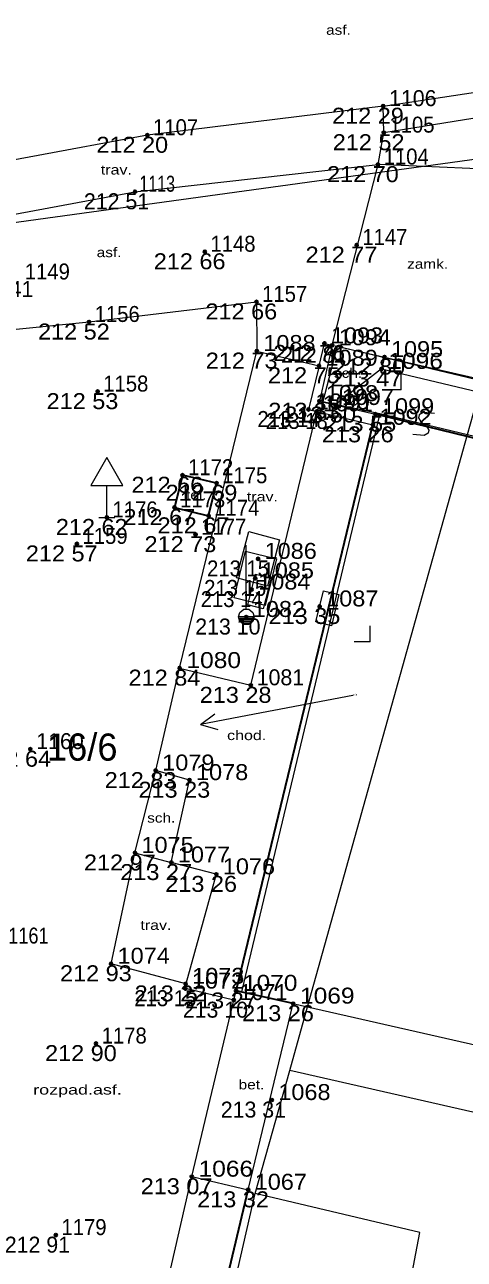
# Model space of a CAD drawing. Extents: x -736847 to -736508, y -1028413 to -1028271.
# Drawn here: x -736642.58 to -736628.79, y -1028331.58 to -1028292.91 of the extents above; entities that cross this region are included whole.
import ezdxf
from ezdxf.enums import TextEntityAlignment as Align

# ---------------------------------------------------------------- set-up
doc = ezdxf.new("R2010")
doc.units = 0
doc.header["$LTSCALE"] = 0.2
doc.header["$PDMODE"] = 32
doc.header["$PDSIZE"] = 0.1
for name, color, linetype, lineweight in [('1', 7, 'Continuous', 13), ('13', 7, 'Continuous', 13), ('14', 7, 'Continuous', 13), ('2', 7, 'Continuous', 13), ('6', 7, 'Continuous', 35), ('63', 7, 'Continuous', 13), ('8', 7, 'Continuous', 13)]:
    doc.layers.add(name, color=color, linetype=linetype, lineweight=lineweight)
for name, color, linetype in [('34', 7, 'Continuous'), ('35', 7, 'Continuous'), ('36', 7, 'Continuous'), ('60', 7, 'Continuous')]:
    doc.layers.add(name, color=color, linetype=linetype)

msp = doc.modelspace()

# ---------------------------------------------------------------- linework, layer by layer
at = {"layer": '1'}
for p, q in [((-736631.44, -1028305.09), (-736635.78, -1028323.2)), ((-736633.23, -1028304.71), (-736631.44, -1028305.09)), ((-736632.29, -1028313.92), (-736635.59, -1028314.55)), ((-736635.78, -1028323.2), (-736633.71, -1028323.67)), ((-736634.27, -1028325.67), (-736633.71, -1028323.67)), ((-736618.4, -1028329.27), (-736634.27, -1028325.67)), ((-736630.19, -1028330.74), (-736635.35, -1028329.52)), ((-736632.11, -1028340.7), (-736630.19, -1028330.74))]:
    msp.add_line(p, q, dxfattribs=at)
for points in [[(-736617.32, -1028295.6), (-736658.87, -1028301.31), (-736705.21, -1028307.67), (-736744.41, -1028313.05)], [(-736628.23, -1028304.07), (-736632.78, -1028302.99), (-736633.23, -1028304.71)], [(-736633.71, -1028323.67), (-736628.7, -1028305.74), (-736628.23, -1028304.07), (-736628.08, -1028303.52), (-736613.31, -1028306.89)], [(-736631.44, -1028305.09), (-736628.7, -1028305.74), (-736619.51, -1028307.93), (-736613.83, -1028309.17)], [(-736633.71, -1028323.67), (-736623.82, -1028325.92), (-736619.51, -1028307.93)], [(-736637.65, -1028339.56), (-736635.35, -1028329.52), (-736634.27, -1028325.67)]]:
    msp.add_lwpolyline(points, dxfattribs=at)
at = {"layer": '13'}
for p, q in [((-736632.94, -1028302.95), (-736631.5, -1028297.29)), ((-736636.57, -1028319.52), (-736637.98, -1028319.15)), ((-736636.57, -1028319.52), (-736637.53, -1028322.95)), ((-736637.53, -1028322.95), (-736639.87, -1028322.32)), ((-736636.02, -1028323.46), (-736635.95, -1028323.17))]:
    msp.add_line(p, q, dxfattribs=at)
for points in [[(-736631.34, -1028295.46), (-736623.55, -1028294.28), (-736616.25, -1028293.04)], [(-736631.32, -1028296.29), (-736623.21, -1028294.98), (-736616.18, -1028294.11)], [(-736647.39, -1028299.68), (-736647.28, -1028301.52), (-736646.39, -1028302.8), (-736640.56, -1028302.22), (-736640.56, -1028302.22), (-736635.31, -1028301.59), (-736635.3, -1028303.13)], [(-736637.72, -1028313.06), (-736635.49, -1028313.6), (-736633.42, -1028305.02)], [(-736636.02, -1028323.46), (-736637.54, -1028323.1), (-736637.53, -1028322.95)], [(-736636.35, -1028348.87), (-736638.02, -1028347.6), (-736639.98, -1028345.87), (-736640.72, -1028342.81), (-736639.05, -1028336.46), (-736637.34, -1028328.99)]]:
    msp.add_lwpolyline(points, dxfattribs=at)
msp.add_lwpolyline([(-736631.5, -1028297.29), (-736631.32, -1028296.29), (-736631.34, -1028295.46), (-736638.73, -1028296.37), (-736646.16, -1028297.75), (-736647.51, -1028298.95), (-736647.39, -1028299.68), (-736639.12, -1028298.14)], close=True, dxfattribs=at)
at = {"layer": '14'}
msp.add_lwpolyline([(-736624, -1028304.98), (-736622.43, -1028297.74), (-736626.7, -1028297.5), (-736631.5, -1028297.29)], dxfattribs=at)
at = {"layer": '2'}
for p, q in [((-736630.78, -1028304.35), (-736630.78, -1028303.85)), ((-736630.78, -1028304.35), (-736631.28, -1028304.35)), ((-736631.75, -1028312.24), (-736631.75, -1028311.74)), ((-736631.75, -1028312.24), (-736632.25, -1028312.24)), ((-736637.063, -1028314.83), (-736636.619, -1028314.491))]:
    msp.add_line(p, q, dxfattribs=at)
for points in [[(-736629.734, -1028305.083), (-736630.086, -1028305.051), (-736630.206, -1028305.125), (-736630.229, -1028305.222), (-736630.155, -1028305.343), (-736629.984, -1028305.486), (-736629.91, -1028305.607), (-736629.933, -1028305.704), (-736630.053, -1028305.778), (-736630.405, -1028305.746)], [(-736635.59, -1028314.55), (-736637.063, -1028314.83), (-736636.525, -1028314.982)]]:
    msp.add_lwpolyline(points, dxfattribs=at)
at = {"layer": '34'}
for p in [(-736631.34, -1028295.46), (-736638.73, -1028296.37), (-736631.32, -1028296.29), (-736631.5, -1028297.29), (-736639.12, -1028298.14), (-736636.93, -1028300.02), (-736632.17, -1028299.81), (-736635.31, -1028301.59), (-736640.56, -1028302.22), (-736635.3, -1028303.13), (-736633.18, -1028302.89), (-736632.94, -1028302.95), (-736633.35, -1028303.59), (-736631.3, -1028303.32), (-736631.39, -1028303.69), (-736640.29, -1028304.4), (-736633.34, -1028304.7), (-736633.68, -1028304.96), (-736633.42, -1028305.02), (-736632.84, -1028304.82), (-736631.58, -1028305.11), (-736631.66, -1028305.44), (-736637.63, -1028307.02), (-736636.56, -1028307.27), (-736637.88, -1028308.03), (-736640, -1028308.34), (-736636.81, -1028308.29), (-736637.22, -1028308.88), (-736640.94, -1028309.17), (-736635.26, -1028309.64), (-736635.35, -1028310.25), (-736635.46, -1028310.6), (-736633.33, -1028311.13), (-736635.63, -1028311.46), (-736637.72, -1028313.06), (-736635.49, -1028313.6), (-736642.4, -1028315.6), (-736638.47, -1028316.27), (-736637.41, -1028316.57), (-736639.12, -1028318.85), (-736637.98, -1028319.15), (-736636.57, -1028319.52), (-736639.87, -1028322.32), (-736637.54, -1028323.1), (-736637.53, -1028322.95), (-736635.95, -1028323.17), (-736636.02, -1028323.46), (-736634.16, -1028323.57), (-736640.34, -1028324.82), (-736634.83, -1028326.59), (-736637.34, -1028328.99), (-736635.57, -1028329.4), (-736641.6, -1028330.82)]:
    msp.add_point(p, dxfattribs=at)
at = {"layer": '6'}
for p, q in [((-736619.67, -1028308), (-736631.58, -1028305.11)), ((-736639.57, -1028346.1), (-736635.57, -1028329.4))]:
    msp.add_line(p, q, dxfattribs=at)
msp.add_lwpolyline([(-736634.16, -1028323.57), (-736635.95, -1028323.17), (-736631.66, -1028305.44), (-736631.58, -1028305.11)], dxfattribs=at)
msp.add_lwpolyline([(-736637.63, -1028307.02), (-736637.88, -1028308.03), (-736636.81, -1028308.29), (-736636.56, -1028307.27)], close=True, dxfattribs=at)
at = {"layer": '63'}
msp.add_line((-736635.63, -1028311.22), (-736635.63, -1028309.21), dxfattribs=at)
for points in [[(-736634.968, -1028310.492), (-736635.935, -1028310.237), (-736635.551, -1028308.787), (-736634.584, -1028309.042)], [(-736635.04, -1028311.096), (-736636.012, -1028310.861), (-736635.659, -1028309.403), (-736634.687, -1028309.638)], [(-736635.337, -1028310.115), (-736634.853, -1028310.237), (-736635.097, -1028311.206), (-736635.582, -1028311.084)], [(-736633.212, -1028310.644), (-736632.726, -1028310.761), (-736632.961, -1028311.733), (-736633.447, -1028311.615)]]:
    msp.add_lwpolyline(points, close=True, dxfattribs=at)
msp.add_lwpolyline([(-736635.55, -1028311.7), (-736635.71, -1028311.7), (-736635.83, -1028311.605), (-736635.87, -1028311.46), (-736635.83, -1028311.315), (-736635.71, -1028311.22), (-736635.55, -1028311.22), (-736635.43, -1028311.315), (-736635.38, -1028311.46), (-736635.43, -1028311.605), (-736635.55, -1028311.7), (-736635.75, -1028311.66), (-736635.51, -1028311.66), (-736635.47, -1028311.62), (-736635.79, -1028311.62), (-736635.83, -1028311.58), (-736635.43, -1028311.58), (-736635.43, -1028311.54), (-736635.83, -1028311.54), (-736635.83, -1028311.5), (-736635.43, -1028311.5), (-736635.39, -1028311.46), (-736635.87, -1028311.46)], dxfattribs=at)
at = {"layer": '8'}
for p, q in [((-736633.35, -1028303.59), (-736633.18, -1028302.89)), ((-736633.18, -1028302.89), (-736632.94, -1028302.95)), ((-736632.84, -1028304.82), (-736631.58, -1028305.11)), ((-736640.25, -1028308.34), (-736639.75, -1028308.34)), ((-736639.12, -1028318.85), (-736638.47, -1028316.27)), ((-736639.87, -1028322.32), (-736639.12, -1028318.85)), ((-736637.34, -1028328.99), (-736636.02, -1028323.46)), ((-736635.57, -1028329.4), (-736634.16, -1028323.57)), ((-736637.34, -1028328.99), (-736635.57, -1028329.4))]:
    msp.add_line(p, q, dxfattribs=at)
for points in [[(-736638.47, -1028316.27), (-736637.72, -1028313.06), (-736635.3, -1028303.13), (-736633.35, -1028303.59)], [(-736632.94, -1028302.95), (-736633.34, -1028304.7), (-736632.84, -1028304.82)], [(-736632.94, -1028302.95), (-736631.3, -1028303.32), (-736631.39, -1028303.69), (-736632.84, -1028304.82)], [(-736631.3, -1028303.32), (-736625.01, -1028304.76), (-736619.8, -1028306.05), (-736619.91, -1028306.4)], [(-736633.35, -1028303.59), (-736633.68, -1028304.96), (-736633.42, -1028305.02), (-736631.66, -1028305.44)], [(-736631.39, -1028303.69), (-736625.15, -1028305.17), (-736619.91, -1028306.4)], [(-736640, -1028308.34), (-736640, -1028307.34), (-736639.5, -1028307.34), (-736640, -1028306.465), (-736640.5, -1028307.34), (-736640, -1028307.34)], [(-736639.12, -1028318.85), (-736637.98, -1028319.15), (-736637.41, -1028316.57), (-736638.47, -1028316.27)]]:
    msp.add_lwpolyline(points, dxfattribs=at)

# ---------------------------------------------------------------- texts
at = {"layer": '2'}
msp.add_text('16/6', height=0.05, dxfattribs=at).set_placement((-736632.29, -1028313.92))
msp.add_text('16/6', height=0.85, dxfattribs=at).set_placement((-736639.667, -1028315.96), align=Align.RIGHT)
at = {"layer": '35'}
for s, p in [(' 1106', (-736631.34, -1028295.46)), (' 1081', (-736635.49, -1028313.6)), (' 1160', (-736642.4, -1028315.6)), (' 1071', (-736636.02, -1028323.46))]:
    msp.add_text(s, height=0.5, dxfattribs=at).set_placement(p)
for s, width, p in [(' 1105', 0.95, (-736631.32, -1028296.29)), (' 1107', 0.95, (-736638.73, -1028296.37)), (' 1104', 0.95, (-736631.5, -1028297.29)), (' 1113', 0.75, (-736639.12, -1028298.14)), (' 1148', 0.95, (-736636.93, -1028300.02)), (' 1147', 0.95, (-736632.17, -1028299.81)), (' 1149', 0.95, (-736642.75, -1028300.89)), (' 1157', 0.95, (-736635.31, -1028301.59)), (' 1156', 0.95, (-736640.56, -1028302.22)), (' 1093', 1.1, (-736633.18, -1028302.89)), (' 1088', 1.1, (-736635.3, -1028303.13)), (' 1094', 1.1, (-736632.94, -1028302.95)), (' 1089', 1.1, (-736633.35, -1028303.59)), (' 1095', 1.1, (-736631.3, -1028303.32)), (' 1096', 1.15, (-736631.39, -1028303.69)), (' 1158', 0.95, (-736640.29, -1028304.4)), (' 1098', 1.1, (-736633.34, -1028304.7)), (' 1097', 1.1, (-736632.84, -1028304.82)), (' 1090', 1.15, (-736633.68, -1028304.96)), (' 1091', 1.05, (-736633.42, -1028305.02)), (' 1099', 1.1, (-736631.58, -1028305.11)), (' 1092', 1.1, (-736631.66, -1028305.44)), (' 1172', 0.95, (-736637.63, -1028307.02)), (' 1175', 0.95, (-736636.56, -1028307.27)), (' 1173', 0.95, (-736637.88, -1028308.03)), (' 1174', 0.95, (-736636.81, -1028308.29)), (' 1176', 0.95, (-736640, -1028308.34)), (' 1177', 0.95, (-736637.22, -1028308.88)), (' 1159', 0.95, (-736640.94, -1028309.17)), (' 1086', 1.1, (-736635.26, -1028309.64)), (' 1084', 1.1, (-736635.46, -1028310.6)), (' 1085', 1.1, (-736635.35, -1028310.25)), (' 1087', 1.1, (-736633.33, -1028311.13)), (' 1082', 1.1, (-736635.63, -1028311.46)), (' 1080', 1.15, (-736637.72, -1028313.06)), (' 1079', 1.1, (-736638.47, -1028316.27)), (' 1078', 1.1, (-736637.41, -1028316.57)), (' 1075', 1.1, (-736639.12, -1028318.85)), (' 1077', 1.1, (-736637.98, -1028319.15)), (' 1076', 1.1, (-736636.57, -1028319.52)), (' 1161', 0.85, (-736643.25, -1028321.69)), (' 1074', 1.1, (-736639.87, -1028322.32)), (' 1073', 1.1, (-736637.53, -1028322.95)), (' 1072', 1.1, (-736637.54, -1028323.1)), (' 1070', 1.15, (-736635.95, -1028323.17)), (' 1069', 1.15, (-736634.16, -1028323.57)), (' 1178', 0.95, (-736640.34, -1028324.82)), (' 1068', 1.1, (-736634.83, -1028326.59)), (' 1066', 1.15, (-736637.34, -1028328.99)), (' 1067', 1.1, (-736635.57, -1028329.4)), (' 1179', 0.95, (-736641.6, -1028330.82))]:
    msp.add_text(s, height=0.5, dxfattribs=dict(at, width=width)).set_placement(p)
at = {"layer": '36'}
for s, width, p in [('212 29', 1.1, (-736632.94, -1028296.01)), ('212 20', 1.1, (-736640.33, -1028296.92)), ('212 52', 1.1, (-736632.92, -1028296.84)), ('212 70', 1.1, (-736633.1, -1028297.84)), ('212 66', 1.1, (-736638.53, -1028300.57)), ('212 77', 1.1, (-736633.77, -1028300.36)), ('212 66', 1.1, (-736636.91, -1028302.14)), ('212 52', 1.1, (-736642.16, -1028302.77)), ('212 76', 1.1, (-736634.78, -1028303.44)), ('212 73', 1.1, (-736636.9, -1028303.68)), ('212 80', 1.1, (-736632.9, -1028303.87)), ('212 75', 1.1, (-736634.95, -1028304.14)), ('213 47', 1.1, (-736632.99, -1028304.24)), ('212 53', 1.1, (-736641.89, -1028304.95)), ('213 14', 0.95, (-736635.28, -1028305.51)), ('213 18', 0.95, (-736635.02, -1028305.57)), ('213 33', 1.1, (-736634.94, -1028305.25)), ('213 50', 1.1, (-736634.44, -1028305.37)), ('213 55', 1.1, (-736633.18, -1028305.66)), ('213 26', 1.1, (-736633.26, -1028305.99)), ('212 66', 1.1, (-736639.23, -1028307.57)), ('212 69', 1.1, (-736638.16, -1028307.82)), ('212 67', 1.1, (-736639.48, -1028308.58)), ('212 62', 1.1, (-736641.6, -1028308.89)), ('212 67', 1.1, (-736638.41, -1028308.84)), ('212 73', 1.1, (-736638.82, -1028309.43)), ('212 57', 1.1, (-736642.54, -1028309.72)), ('213 15', 0.95, (-736636.86, -1028310.19)), ('213 15', 0.95, (-736636.95, -1028310.8)), ('213 14', 0.95, (-736637.06, -1028311.15)), ('213 35', 1.1, (-736634.93, -1028311.68)), ('212 84', 1.1, (-736639.32, -1028313.61)), ('213 28', 1.1, (-736637.09, -1028314.15)), ('212 64', 1.1, (-736644, -1028316.15)), ('212 83', 1.1, (-736640.07, -1028316.82)), ('213 23', 1.1, (-736639.01, -1028317.12)), ('212 97', 1.1, (-736640.72, -1028319.4)), ('213 27', 1.1, (-736639.58, -1028319.7)), ('213 26', 1.1, (-736638.17, -1028320.07)), ('212 93', 1.1, (-736641.47, -1028322.87)), ('213 15', 0.95, (-736639.14, -1028323.65)), ('213 22', 1.1, (-736639.13, -1028323.5)), ('213 27', 1.1, (-736637.55, -1028323.72)), ('213 26', 1.1, (-736635.76, -1028324.12)), ('212 90', 1.1, (-736641.94, -1028325.37)), ('213 07', 1.1, (-736638.94, -1028329.54)), ('213 32', 1.1, (-736637.17, -1028329.95))]:
    msp.add_text(s, height=0.5, dxfattribs=dict(at, width=width)).set_placement(p)
for s, p in [('212 51', (-736640.72, -1028298.69)), ('212 41', (-736644.35, -1028301.44)), ('212 81', (-736634.54, -1028303.5)), ('213 10', (-736637.23, -1028312.01)), ('213 10', (-736637.62, -1028324.01)), ('213 31', (-736636.43, -1028327.14)), ('212 91', (-736643.2, -1028331.37))]:
    msp.add_text(s, height=0.5, dxfattribs=at).set_placement(p)
at = {"layer": '60'}
for s, width, p in [('asf.', 1.2, (-736632.74, -1028293.225)), ('trav.', 1.25, (-736639.703, -1028297.602)), ('asf.', 1.2, (-736639.931, -1028300.19)), ('zamk.', 1.2, (-736629.946, -1028300.553)), ('sch.', 1.2, (-736632.439, -1028303.971)), ('tel.', 1.2, (-736637.199, -1028307.787)), ('trav.', 1.25, (-736635.125, -1028307.841)), ('chod.', 1.25, (-736635.618, -1028315.316)), ('sch.', 1.2, (-736638.296, -1028317.902)), ('trav.', 1.25, (-736638.463, -1028321.26)), ('bet.', 1.2, (-736635.468, -1028326.256)), ('rozpad.asf.', 1.4, (-736640.921, -1028326.418))]:
    msp.add_text(s, height=0.3, dxfattribs=dict(at, width=width)).set_placement(p, align=Align.CENTER)

doc.saveas('drawing.dxf')
